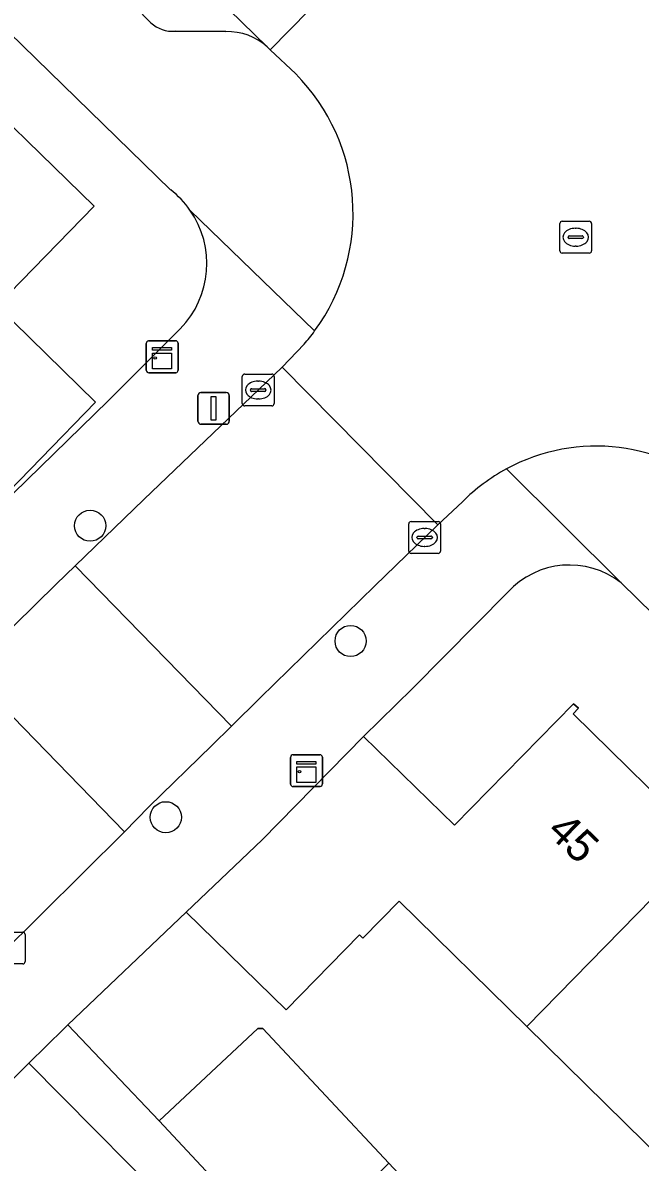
# Model space of a CAD drawing. Extents: x 159217 to 160349, y 381246 to 382172.
# Drawn here: x 159979.23 to 159998.63, y 381745.8 to 381781.59 of the extents above; entities that cross this region are included whole.
import ezdxf

# ---------------------------------------------------------------- set-up
doc = ezdxf.new("R2010")
doc.units = 0
for name, color, linetype in [('IMGEO_Boom', 7, 'Continuous'), ('IMGEO_Erf', 7, 'Continuous'), ('IMGEO_Kast', 7, 'Continuous'), ('IMGEO_Kolk', 7, 'Continuous'), ('IMGEO_Lichtmast', 7, 'Continuous'), ('IMGEO_Pand', 7, 'Continuous'), ('IMGEO_Pand_nummerreeks', 7, 'Continuous'), ('IMGEO_Parkeervlak_open', 7, 'Continuous'), ('IMGEO_Rijbaan_lokaal_gesloten', 7, 'Continuous'), ('IMGEO_Rijbaan_lokaal_open', 7, 'Continuous'), ('IMGEO_Rioolput', 7, 'Continuous'), ('IMGEO_Voetpad_open', 7, 'Continuous')]:
    doc.layers.add(name, color=color, linetype=linetype)

msp = doc.modelspace()

# ---------------------------------------------------------------- linework, layer by layer
at = {"layer": 'IMGEO_Boom'}
for centre in [(159981.349, 381765.792), (159989.532, 381762.17), (159983.726, 381756.634)]:
    msp.add_circle(centre, 0.489, dxfattribs=at)
at = {"layer": 'IMGEO_Erf'}
for points in [[(159983.879, 381776.342), (159944.981, 381814.27)], [(159974.984, 381782.15), (159976.824, 381780.357), (159981.472, 381775.827), (159978.42, 381772.695), (159981.516, 381769.668), (159978.097, 381766.158), (159977.839, 381766.41), (159978.042, 381766.618), (159975.203, 381769.393), (159975.149, 381769.338), (159970.487, 381773.881), (159965.975, 381778.278), (159964.301, 381776.56), (159960.72, 381780.049), (159959.789, 381780.957), (159961.457, 381782.669)], [(159948.65, 381781.627), (159946.792, 381779.78), (159948.356, 381778.17), (159951.879, 381781.709), (159953.722, 381779.875), (159952.027, 381778.173), (159954.583, 381775.629), (159957.521, 381772.706), (159955.673, 381770.849), (159958.821, 381767.68), (159960.678, 381769.528), (159963.477, 381766.717), (159966.418, 381763.763), (159964.562, 381761.914), (159969.165, 381757.287), (159981.918, 381769.715), (159984.182, 381771.978)], [(160066.135, 381697.331), (159998.033, 381763.997)], [(159994.467, 381763.703), (159991.474, 381760.674), (159989.94, 381759.17), (159992.794, 381756.388), (159996.538, 381760.193), (159996.689, 381760.058), (159996.52, 381759.885), (160000.58, 381755.902)], [(159999.385, 381745.823), (159995.07, 381750.065), (159991.063, 381754.001), (159989.921, 381752.837), (159989.814, 381752.941), (159987.513, 381750.581), (159984.366, 381753.65), (159980.644, 381750.109), (159983.513, 381747.093), (159986.62, 381750), (159986.778, 381750), (159990.733, 381745.773), (159993.5, 381742.816), (159990.309, 381739.831), (159991.906, 381738.175), (159994.838, 381740.941), (159998.756, 381736.788)], [(159997.321, 381729.885), (159995.883, 381728.418), (159993.394, 381730.857), (159990.86, 381733.341), (159992.628, 381735.145), (159989.575, 381738.368), (159987.673, 381736.588), (159985.051, 381739.39), (159982.746, 381741.853), (159984.649, 381743.633), (159979.428, 381748.909), (159965.791, 381735.415)]]:
    msp.add_lwpolyline(points, dxfattribs=at)
for centre, radius, start, end in [((159982.093, 381774.034), 2.919, 34.9606, 52.272), ((159982.079, 381774.025), 2.935, 315.7649, 34.9419), ((159996.409, 381761.918), 2.638, 52.0128, 137.4135)]:
    msp.add_arc(centre, radius, start, end, dxfattribs=at)
at = {"layer": 'IMGEO_Kast'}
for p, q in [((159983.113, 381770.673), (159983.113, 381771.514)), ((159983.113, 381771.514), (159983.113, 381770.673)), ((159983.188, 381771.598), (159984.029, 381771.598)), ((159984.029, 381771.598), (159983.188, 381771.598)), ((159984.113, 381771.523), (159984.113, 381770.682)), ((159984.113, 381770.682), (159984.113, 381771.523)), ((159984.038, 381770.598), (159983.197, 381770.598)), ((159983.197, 381770.598), (159984.038, 381770.598)), ((159987.648, 381757.673), (159987.648, 381758.514)), ((159987.648, 381758.514), (159987.648, 381757.673)), ((159987.723, 381758.598), (159988.564, 381758.598)), ((159988.564, 381758.598), (159987.723, 381758.598)), ((159988.648, 381758.523), (159988.648, 381757.682)), ((159988.648, 381757.682), (159988.648, 381758.523)), ((159988.573, 381757.598), (159987.732, 381757.598)), ((159987.732, 381757.598), (159988.573, 381757.598))]:
    msp.add_line(p, q, dxfattribs=at)
for points in [[(159983.308, 381771.388), (159983.908, 381771.388), (159983.908, 381771.303), (159983.308, 381771.303), (159983.308, 381771.388)], [(159983.308, 381771.213), (159983.908, 381771.213), (159983.908, 381770.724), (159983.308, 381770.724), (159983.308, 381771.213)], [(159987.843, 381758.388), (159988.443, 381758.388), (159988.443, 381758.303), (159987.843, 381758.303), (159987.843, 381758.388)], [(159987.843, 381758.213), (159988.443, 381758.213), (159988.443, 381757.724), (159987.843, 381757.724), (159987.843, 381758.213)]]:
    msp.add_lwpolyline(points, dxfattribs=at)
for centre in [(159983.392, 381771.062), (159987.927, 381758.062)]:
    msp.add_circle(centre, 0.0377, dxfattribs=at)
for centre, start, end in [((159983.191, 381771.52), 92.4484, 184.2845), ((159983.191, 381771.52), 92.4484, 184.2845), ((159984.035, 381771.52), 2.4484, 94.2845), ((159984.035, 381771.52), 2.4484, 94.2845), ((159983.191, 381770.676), 182.4484, 274.2845), ((159983.191, 381770.676), 182.4484, 274.2845), ((159984.035, 381770.676), 272.4484, 4.2845), ((159984.035, 381770.676), 272.4484, 4.2845), ((159987.726, 381758.52), 92.4484, 184.2845), ((159987.726, 381758.52), 92.4484, 184.2845), ((159988.57, 381758.52), 2.4484, 94.2845), ((159988.57, 381758.52), 2.4484, 94.2845), ((159987.726, 381757.676), 182.4484, 274.2845), ((159987.726, 381757.676), 182.4484, 274.2845), ((159988.57, 381757.676), 272.4484, 4.2845), ((159988.57, 381757.676), 272.4484, 4.2845)]:
    msp.add_arc(centre, 0.0779, start, end, dxfattribs=at)
at = {"layer": 'IMGEO_Kolk'}
for p, q in [((159986.13, 381769.627), (159986.13, 381770.479)), ((159986.205, 381770.553), (159987.057, 381770.553)), ((159987.131, 381770.479), (159987.131, 381769.627)), ((159986.432, 381770.096), (159986.83, 381770.096)), ((159986.618, 381770.333), (159986.643, 381770.333)), ((159986.389, 381770.047), (159986.389, 381770.059)), ((159986.827, 381770.01), (159986.429, 381770.01)), ((159986.641, 381769.773), (159986.616, 381769.773)), ((159986.873, 381770.059), (159986.873, 381770.047)), ((159987.057, 381769.553), (159986.205, 381769.553)), ((159991.358, 381764.997), (159991.358, 381765.849)), ((159991.433, 381765.923), (159992.285, 381765.923)), ((159992.359, 381765.849), (159992.359, 381764.997)), ((159991.617, 381765.417), (159991.617, 381765.429)), ((159991.66, 381765.466), (159992.058, 381765.466)), ((159991.846, 381765.703), (159991.871, 381765.703)), ((159992.101, 381765.429), (159992.101, 381765.417)), ((159992.055, 381765.38), (159991.657, 381765.38)), ((159991.869, 381765.143), (159991.844, 381765.143)), ((159992.285, 381764.923), (159991.433, 381764.923)), ((159978.381, 381753.025), (159979.233, 381753.025)), ((159979.307, 381752.951), (159979.307, 381752.099)), ((159979.233, 381752.025), (159978.381, 381752.025))]:
    msp.add_line(p, q, dxfattribs=at)
for points in [[(159986.13, 381769.627), (159986.13, 381770.479)], [(159986.205, 381770.553), (159987.057, 381770.553)], [(159987.131, 381770.479), (159987.131, 381769.627)], [(159987.057, 381769.553), (159986.205, 381769.553)], [(159991.358, 381764.997), (159991.358, 381765.849)], [(159991.433, 381765.923), (159992.285, 381765.923)], [(159992.359, 381765.849), (159992.359, 381764.997)], [(159992.285, 381764.923), (159991.433, 381764.923)], [(159978.381, 381753.025), (159979.233, 381753.025)], [(159979.307, 381752.951), (159979.307, 381752.099)], [(159979.233, 381752.025), (159978.381, 381752.025)]]:
    msp.add_lwpolyline(points, dxfattribs=at)
for centre, radius, start, end in [((159986.207, 381770.477), 0.0765, 91.552, 178.448), ((159986.207, 381770.477), 0.0765, 91.552, 178.448), ((159987.055, 381770.477), 0.0765, 1.552, 88.448), ((159987.055, 381770.477), 0.0765, 1.552, 88.448), ((159986.429, 381770.056), 0.0403, 85.8775, 175.7526), ((159986.834, 381770.058), 0.0386, 1.7309, 96.639), ((159986.426, 381770.046), 0.0366, 178.938, 274.7102), ((159986.83, 381770.053), 0.043, 264.8664, 352.4533), ((159986.207, 381769.629), 0.0765, 181.552, 268.448), ((159986.207, 381769.629), 0.0765, 181.552, 268.448), ((159987.055, 381769.629), 0.0765, 271.552, 358.448), ((159987.055, 381769.629), 0.0765, 271.552, 358.448), ((159991.435, 381765.847), 0.0765, 91.552, 178.448), ((159991.435, 381765.847), 0.0765, 91.552, 178.448), ((159992.283, 381765.847), 0.0765, 1.552, 88.448), ((159992.283, 381765.847), 0.0765, 1.552, 88.448), ((159991.657, 381765.426), 0.0403, 85.8775, 175.7526), ((159992.062, 381765.428), 0.0386, 1.7309, 96.639), ((159991.654, 381765.416), 0.0366, 178.938, 274.7102), ((159992.058, 381765.423), 0.043, 264.8664, 352.4533), ((159991.435, 381764.999), 0.0765, 181.552, 268.448), ((159991.435, 381764.999), 0.0765, 181.552, 268.448), ((159992.283, 381764.999), 0.0765, 271.552, 358.448), ((159992.283, 381764.999), 0.0765, 271.552, 358.448), ((159979.231, 381752.949), 0.0765, 1.552, 88.448), ((159979.231, 381752.949), 0.0765, 1.552, 88.448), ((159979.231, 381752.101), 0.0765, 271.552, 358.448), ((159979.231, 381752.101), 0.0765, 271.552, 358.448)]:
    msp.add_arc(centre, radius, start, end, dxfattribs=at)
for centre, major_axis, ratio, start_param, end_param in [((159986.617, 381770.053), (-0.387, 0.002), 0.722429, 4.712389, 7.853982), ((159986.642, 381770.053), (-0.39, 0.002), 0.717154, 1.570796, 4.712389), ((159991.845, 381765.423), (-0.387, 0.002), 0.722429, 4.712389, 7.853982), ((159991.87, 381765.423), (-0.39, 0.002), 0.717154, 1.570796, 4.712389)]:
    msp.add_ellipse(centre, major_axis=major_axis, ratio=ratio, start_param=start_param, end_param=end_param, dxfattribs=at)
at = {"layer": 'IMGEO_Lichtmast'}
for p, q in [((159984.731, 381769.078), (159984.731, 381769.878)), ((159984.731, 381769.878), (159984.731, 381769.078)), ((159984.831, 381769.978), (159985.621, 381769.978)), ((159985.621, 381769.978), (159984.831, 381769.978)), ((159985.721, 381769.878), (159985.721, 381769.078)), ((159985.721, 381769.078), (159985.721, 381769.878)), ((159985.621, 381768.978), (159984.831, 381768.978)), ((159984.831, 381768.978), (159985.621, 381768.978))]:
    msp.add_line(p, q, dxfattribs=at)
msp.add_lwpolyline([(159985.151, 381769.853), (159985.301, 381769.853), (159985.301, 381769.103), (159985.151, 381769.103), (159985.151, 381769.853)], dxfattribs=at)
for centre, start, end in [((159984.831, 381769.878), 90, 180), ((159984.831, 381769.878), 90, 180), ((159985.621, 381769.878), 0, 90), ((159985.621, 381769.878), 360, 90), ((159984.831, 381769.078), 180, 270), ((159984.831, 381769.078), 180, 270), ((159985.621, 381769.078), 270, 0), ((159985.621, 381769.078), 270, 0)]:
    msp.add_arc(centre, 0.1, start, end, dxfattribs=at)
at = {"layer": 'IMGEO_Pand'}
for points in [[(159970.487, 381773.881), (159975.149, 381769.338), (159975.203, 381769.393), (159978.042, 381766.618), (159977.839, 381766.41), (159978.097, 381766.158), (159981.516, 381769.668), (159978.42, 381772.695), (159981.472, 381775.827), (159976.824, 381780.357)], [(159996.52, 381759.885), (159996.689, 381760.058), (159996.538, 381760.193), (159992.794, 381756.388), (159989.94, 381759.17), (159986.756, 381755.923), (159984.366, 381753.65), (159987.513, 381750.581), (159989.814, 381752.941), (159989.921, 381752.837), (159991.063, 381754.001), (159995.07, 381750.065), (160000, 381755.094), (160000.954, 381756.067), (160000.849, 381756.171), (160000.58, 381755.902)], [(159995.07, 381750.065), (159999.385, 381745.823), (160000, 381746.45), (160003.48, 381750), (160005.255, 381751.81), (160005.13, 381751.934), (160004.899, 381751.699), (160000.817, 381755.717), (160001.06, 381755.963), (160000.954, 381756.067), (160000, 381755.094)], [(159990.733, 381745.773), (159986.778, 381750), (159986.62, 381750), (159983.513, 381747.093), (159987.625, 381742.699)]]:
    msp.add_lwpolyline(points, close=True, dxfattribs=at)
at = {"layer": 'IMGEO_Parkeervlak_open'}
for points in [[(159986.909, 381780.832), (159947.87, 381818.841)], [(159980.485, 381786.066), (159979.677, 381785.254), (159983.261, 381781.589)], [(159984.016, 381781.325), (159985.616, 381781.311)]]:
    msp.add_lwpolyline(points, dxfattribs=at)
for centre, radius, start, end in [((159983.935, 381782.306), 0.984, 226.7489, 274.7048), ((159985.675, 381779.486), 1.826, 47.4948, 91.8502)]:
    msp.add_arc(centre, radius, start, end, dxfattribs=at)
at = {"layer": 'IMGEO_Rijbaan_lokaal_gesloten'}
msp.add_lwpolyline([(159948.826, 381820.271), (159947.654, 381819.044), (159947.87, 381818.841), (159986.909, 381780.832), (159987.009, 381780.736), (159988.232, 381781.989)], close=True, dxfattribs=at)
at = {"layer": 'IMGEO_Rijbaan_lokaal_open'}
for points in [[(159991.973, 381783.59), (159990.828, 381784.721), (159989.625, 381783.442), (159988.232, 381781.989), (159987.009, 381780.736), (159987.807, 381779.983)], [(159988.069, 381771.493), (159987.385, 381770.773), (159992.268, 381765.818), (159993.044, 381766.543)], [(159964.09, 381737.995), (159982.428, 381756.18), (159977.503, 381761.23), (159973.323, 381757.123), (159967.429, 381751.315), (159966.126, 381750), (159961.743, 381745.577), (159959.666, 381743.451), (159958.803, 381742.588), (159953.054, 381736.646), (159944.522, 381727.792), (159942.659, 381725.828), (159941.73, 381724.849), (159946.781, 381720.023), (159947.694, 381720.953), (159951.478, 381724.809), (159952.525, 381725.938), (159963.213, 381736.961)]]:
    msp.add_lwpolyline(points, dxfattribs=at)
for points in [[(159990.289, 381763.908), (159992.268, 381765.818), (159987.385, 381770.773), (159983.039, 381766.619), (159980.881, 381764.533), (159985.791, 381759.5), (159986.691, 381760.388)], [(159980.881, 381764.533), (159980.287, 381763.953), (159978.303, 381762.016), (159977.503, 381761.23), (159982.428, 381756.18), (159983.195, 381756.957), (159985.168, 381758.885), (159985.791, 381759.5)]]:
    msp.add_lwpolyline(points, close=True, dxfattribs=at)
for centre, radius, start, end in [((159983.369, 381775.597), 6.24, 323.762, 44.6663), ((159983.395, 381775.584), 6.211, 318.8012, 323.711), ((159997.251, 381762.356), 5.935, 47.7079, 118.3898), ((159997.274, 381762.327), 5.972, 118.4476, 135.0934)]:
    msp.add_arc(centre, radius, start, end, dxfattribs=at)
at = {"layer": 'IMGEO_Rioolput'}
for p, q in [((159996.104, 381774.428), (159996.104, 381775.28)), ((159996.179, 381775.354), (159997.031, 381775.354)), ((159996.592, 381775.134), (159996.617, 381775.134)), ((159997.105, 381775.28), (159997.105, 381774.428)), ((159996.363, 381774.848), (159996.363, 381774.86)), ((159996.801, 381774.811), (159996.403, 381774.811)), ((159996.406, 381774.897), (159996.804, 381774.897)), ((159996.847, 381774.86), (159996.847, 381774.848)), ((159996.615, 381774.574), (159996.59, 381774.574)), ((159997.031, 381774.354), (159996.179, 381774.354))]:
    msp.add_line(p, q, dxfattribs=at)
for points in [[(159996.104, 381774.428), (159996.104, 381775.28)], [(159996.179, 381775.354), (159997.031, 381775.354)], [(159997.105, 381775.28), (159997.105, 381774.428)], [(159997.031, 381774.354), (159996.179, 381774.354)]]:
    msp.add_lwpolyline(points, dxfattribs=at)
for centre, radius, start, end in [((159996.181, 381775.278), 0.0765, 91.552, 178.448), ((159996.181, 381775.278), 0.0765, 91.552, 178.448), ((159997.029, 381775.278), 0.0765, 1.552, 88.448), ((159997.029, 381775.278), 0.0765, 1.552, 88.448), ((159996.403, 381774.857), 0.0403, 85.8775, 175.7526), ((159996.4, 381774.847), 0.0366, 178.938, 274.7102), ((159996.804, 381774.854), 0.043, 264.8664, 352.4533), ((159996.808, 381774.859), 0.0386, 1.7309, 96.639), ((159996.181, 381774.43), 0.0765, 181.552, 268.448), ((159996.181, 381774.43), 0.0765, 181.552, 268.448), ((159997.029, 381774.43), 0.0765, 271.552, 358.448), ((159997.029, 381774.43), 0.0765, 271.552, 358.448)]:
    msp.add_arc(centre, radius, start, end, dxfattribs=at)
for centre, major_axis, ratio, start_param, end_param in [((159996.591, 381774.854), (-0.387, 0.002), 0.722429, 4.712389, 7.853982), ((159996.616, 381774.854), (-0.39, 0.002), 0.717154, 1.570796, 4.712389)]:
    msp.add_ellipse(centre, major_axis=major_axis, ratio=ratio, start_param=start_param, end_param=end_param, dxfattribs=at)
at = {"layer": 'IMGEO_Voetpad_open'}
for points in [[(159944.981, 381814.27), (159983.879, 381776.342)], [(159983.261, 381781.589), (159979.677, 381785.254), (159980.485, 381786.066)], [(159985.616, 381781.311), (159984.016, 381781.325)], [(159987.807, 381779.983), (159987.009, 381780.736), (159986.909, 381780.832)], [(159988.402, 381771.908), (159984.485, 381775.706)], [(159984.485, 381775.706), (159988.402, 381771.908)], [(159984.182, 381771.978), (159981.918, 381769.715), (159969.165, 381757.287), (159968.081, 381756.217), (159965.783, 381753.926), (159961.845, 381750), (159961.219, 381749.376), (159951.102, 381739.016)], [(159987.385, 381770.773), (159988.069, 381771.493)], [(159961.743, 381745.577), (159966.126, 381750), (159967.429, 381751.315), (159973.323, 381757.123), (159977.503, 381761.23), (159978.303, 381762.016), (159980.287, 381763.953), (159980.881, 381764.533), (159983.039, 381766.619), (159987.385, 381770.773)], [(159994.429, 381767.578), (159998.033, 381763.997), (160066.135, 381697.331), (160068.335, 381695.177), (160078.491, 381685.188), (160083.645, 381677.305), (160084.945, 381675.203), (160085.845, 381675.766)], [(159998.033, 381763.997), (159994.429, 381767.578)], [(159993.044, 381766.543), (159992.268, 381765.818), (159990.289, 381763.908), (159986.691, 381760.388), (159985.791, 381759.5), (159985.168, 381758.885), (159983.195, 381756.957), (159982.428, 381756.18), (159964.09, 381737.995)], [(159980.53, 381750), (159980.644, 381750.109), (159984.366, 381753.65), (159986.756, 381755.923), (159989.94, 381759.17), (159991.474, 381760.674), (159994.467, 381763.703)], [(160000.021, 381729.573), (159995.84, 381734.005), (159991.906, 381738.175), (159990.309, 381739.831), (159987.625, 381742.699), (159983.513, 381747.093), (159980.644, 381750.109), (159980.53, 381750), (159979.428, 381748.909), (159984.649, 381743.633), (159987.061, 381741.055), (159989.575, 381738.368), (159992.628, 381735.145), (159995.35, 381732.477), (159997.651, 381730.222), (159997.321, 381729.885), (160000.571, 381726.7)], [(159962.426, 381732.044), (159965.791, 381735.415), (159979.428, 381748.909), (159980.53, 381750)]]:
    msp.add_lwpolyline(points, dxfattribs=at)
for centre, radius, start, end in [((159983.935, 381782.306), 0.984, 226.7489, 274.7048), ((159985.675, 381779.486), 1.826, 47.4948, 91.8502), ((159983.369, 381775.597), 6.24, 323.762, 44.6663), ((159982.093, 381774.034), 2.919, 34.9606, 52.272), ((159982.079, 381774.025), 2.935, 315.7649, 34.9419), ((159983.395, 381775.584), 6.211, 318.8012, 323.711), ((159997.251, 381762.356), 5.935, 47.7079, 118.3898), ((159997.274, 381762.327), 5.972, 118.4476, 135.0934), ((159996.409, 381761.918), 2.638, 52.0128, 137.4135)]:
    msp.add_arc(centre, radius, start, end, dxfattribs=at)

# ---------------------------------------------------------------- texts
at = {"layer": 'IMGEO_Pand_nummerreeks'}
msp.add_text('45', height=1, rotation=315.8651, dxfattribs=at).set_placement((159995.658, 381756.152))

doc.saveas('drawing.dxf')
